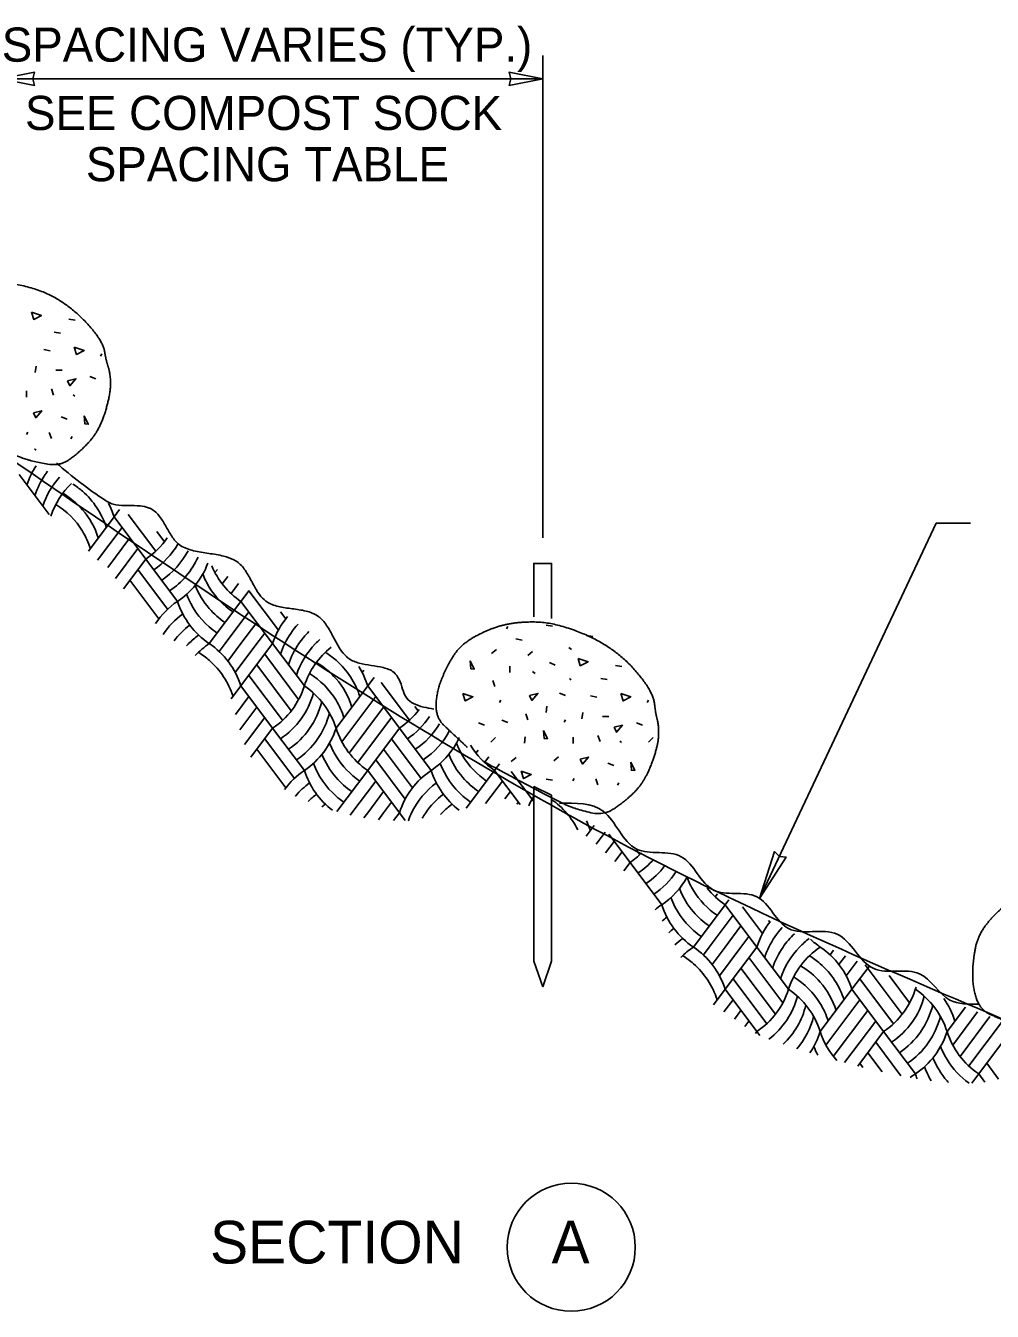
# Model space of a CAD drawing. Extents: x 99862 to 103680, y 99470 to 102076.
# Drawn here: x 101718 to 102171, y 100755 to 101357 of the extents above; entities that cross this region are included whole.
import ezdxf

# ---------------------------------------------------------------- set-up
doc = ezdxf.new("R2010")
doc.units = 0
for name, color, linetype in [('Level 1', 7, 'Continuous'), ('Level 15', 7, 'Continuous'), ('Level 2', 7, 'Continuous'), ('Level 20', 7, 'Continuous'), ('Level 5', 7, 'Continuous'), ('Level 8', 7, 'Continuous')]:
    doc.layers.add(name, color=color, linetype=linetype)

msp = doc.modelspace()

# ---------------------------------------------------------------- linework, layer by layer
at = {"layer": 'Level 1'}
for points in [[(101679, 101169.6), (101713.94, 101155.29), (101722.33, 101152.8), (101733.67, 101150.75), (101742.6, 101156.76), (101752.6, 101167.59), (101757.92, 101185.54), (101757.37, 101195.19), (101755.63, 101199.86), (101754.11, 101209.17), (101741.6, 101223.5), (101725.73, 101233.48), (101704.82, 101237.69), (101688.7, 101238.98), (101676.01, 101235.17), (101662.34, 101226.63), (101656.02, 101214.64), (101652.47, 101202.67), (101653.18, 101191.71), (101654.52, 101177.27), (101669.65, 101172.39)], [(101932.12, 101012.62), (101968.6, 100992.9), (101976.82, 100989.9), (101988.01, 100987.17), (101997.29, 100992.63), (102007.93, 101002.83), (102014.34, 101020.42), (102014.37, 101030.09), (102012.92, 101034.85), (102011.97, 101044.24), (102000.35, 101059.3), (101985.11, 101070.23), (101964.62, 101077.69), (101948.49, 101077.97), (101935.59, 101074.94), (101921.43, 101067.25), (101914.39, 101055.66), (101910.12, 101043.93), (101910.16, 101032.94), (101917.43, 101025.96), (101924.75, 101019.11)], [(102192.84, 100884.38), (102233.87, 100878.32), (102242.62, 100878.32), (102254.07, 100879.59), (102260.92, 100887.89), (102267.43, 100901.12), (102267.43, 100919.84), (102264.15, 100928.93), (102261.16, 100932.91), (102257.06, 100941.41), (102240.99, 100951.59), (102222.93, 100956.64), (102201.12, 100956.64), (102185.87, 100951.38), (102174.78, 100944.12), (102164.11, 100932.05), (102161.46, 100918.76), (102161.46, 100906.27), (102165.26, 100895.96), (102174.48, 100891.89), (102183.7, 100887.96)]]:
    msp.add_open_spline(points, degree=2, dxfattribs=at)
at = {"layer": 'Level 15'}
for p, q in [((101960.08, 101117.27), (101960.08, 101343.16)), ((101706.31, 101332.26), (101960.08, 101332.26)), ((102061.66, 100948.34), (102144.42, 101124.12)), ((102160.42, 101124.12), (102144.42, 101124.12))]:
    msp.add_line(p, q, dxfattribs=at)
for points in [[(101706.31, 101332.26), (101722.04, 101329.18), (101721.31, 101332.26), (101722.04, 101335.35)], [(101960.08, 101332.26), (101944.35, 101329.18), (101945.08, 101332.26), (101944.35, 101335.35)], [(102061.66, 100948.34), (102074.05, 100967.74), (102070.9, 100968.05), (102068.65, 100970.28)]]:
    msp.add_lwpolyline(points, close=True, dxfattribs=at)
at = {"layer": 'Level 2'}
for p, q in [((101738.12, 101219.69), (101741.07, 101219.16)), ((101731.23, 101213.61), (101734.19, 101213.07)), ((101726.42, 101205.43), (101729.37, 101204.9)), ((101753.59, 101203.47), (101752.97, 101202.37)), ((101722.76, 101197.65), (101722.39, 101194.67)), ((101731.97, 101195.74), (101734.97, 101195.74)), ((101747.97, 101192.83), (101750.76, 101191.71)), ((101718.32, 101186.14), (101718.32, 101183.14)), ((101730.94, 101184.13), (101729.93, 101186.96)), ((101740.15, 101184.23), (101740.93, 101183.6)), ((101734.55, 101173.97), (101737.34, 101172.85)), ((101718.85, 101166.71), (101718.23, 101165.61)), ((101729.93, 101163.73), (101728.92, 101166.55)), ((101739.68, 101164.67), (101739.06, 101163.58)), ((101721.98, 101158.89), (101722.76, 101158.26)), ((101943.77, 101075.78), (101943.15, 101074.69)), ((101961.68, 101076.37), (101964.63, 101075.83)), ((101947.51, 101069.88), (101950.46, 101069.35)), ((101980.52, 101071.54), (101983.48, 101071.01)), ((101936.14, 101063.01), (101938.42, 101064.96)), ((101953.03, 101062.1), (101955.3, 101064.05)), ((101972.38, 101065.93), (101973.63, 101064.99)), ((101963.19, 101058.79), (101965.97, 101057.67)), ((101944.63, 101057.2), (101944.63, 101054.2)), ((101955.34, 101054.67), (101956.59, 101053.73)), ((101994.14, 101057.44), (101997.1, 101056.91)), ((101937.69, 101047.68), (101936.68, 101050.5)), ((101972.69, 101051.38), (101973.47, 101050.76)), ((101987.26, 101051.36), (101990.21, 101050.82)), ((101940.42, 101041.22), (101939.79, 101040.12)), ((101968.01, 101044.45), (101970.8, 101043.34)), ((101982.45, 101043.18), (101985.4, 101042.65)), ((102009.62, 101041.22), (102009, 101040.12)), ((101953.11, 101031.98), (101952.1, 101034.8)), ((101961.97, 101038.4), (101961.68, 101035.41)), ((101978.79, 101035.4), (101978.42, 101032.42)), ((101988, 101033.49), (101991, 101033.49)), ((101930.02, 101030.57), (101932.81, 101029.46)), ((101940.92, 101031.82), (101943.74, 101030.81)), ((101970.82, 101031.98), (101970.19, 101030.89)), ((102004, 101030.57), (102006.78, 101029.46)), ((101935.71, 101021.61), (101937.91, 101023.65)), ((101951.87, 101024.07), (101951.58, 101021.08)), ((101974.34, 101023.89), (101974.34, 101020.89)), ((101986.96, 101021.88), (101985.96, 101024.7)), ((101996.18, 101021.97), (101996.96, 101021.35)), ((102009.69, 101021.61), (102011.88, 101023.65)), ((101945.34, 101012.47), (101947.62, 101014.42)), ((101965.24, 101012.77), (101967.52, 101014.72)), ((101990.58, 101011.72), (101993.37, 101010.6)), ((101961.68, 101004.26), (101964.63, 101003.72)), ((101974.88, 101004.46), (101974.25, 101003.36)), ((101985.96, 101001.48), (101984.95, 101004.3)), ((101955.9, 101000.8), (101955.9, 100918.89)), ((101964.25, 100996.64), (101955.9, 101000.8)), ((101995.71, 101002.42), (101995.08, 101001.33)), ((101964.25, 100918.89), (101964.25, 100996.64)), ((101955.9, 100918.89), (101960.08, 100907)), ((101960.08, 100907), (101964.25, 100918.89))]:
    msp.add_line(p, q, dxfattribs=at)
for points in [[(101720.57, 101223.02), (101721.67, 101219.58), (101725.26, 101221.46)], [(101740.62, 101206.6), (101741.72, 101203.16), (101745.31, 101205.03)], [(101737.49, 101190.79), (101738.59, 101188.45), (101741.4, 101191.73)], [(101721.53, 101175.85), (101722.63, 101173.5), (101725.44, 101176.78)], [(101745.31, 101174.37), (101747.19, 101170.46), (101745.62, 101170.62)], [(101926.11, 101059.67), (101927.99, 101055.76), (101926.42, 101055.92)], [(101976.6, 101060.77), (101977.69, 101057.33), (101981.29, 101059.2)], [(101922.67, 101044.35), (101923.77, 101040.9), (101927.36, 101042.78)], [(101953.93, 101043.46), (101955.03, 101041.12), (101957.84, 101044.4)], [(101996.65, 101044.35), (101997.74, 101040.9), (102001.34, 101042.78)], [(101993.52, 101028.54), (101994.61, 101026.2), (101997.43, 101029.48)], [(101960.37, 101027.06), (101962.24, 101023.15), (101960.68, 101023.3)], [(101977.56, 101013.59), (101978.65, 101011.25), (101981.47, 101014.53)], [(102001.34, 101012.12), (102003.21, 101008.21), (102001.65, 101008.37)], [(101950.03, 101007.9), (101951.12, 101004.46), (101954.72, 101006.33)]]:
    msp.add_lwpolyline(points, close=True, dxfattribs=at)
msp.add_lwpolyline([(101955.9, 101080.22), (101955.9, 101105.27), (101964.25, 101105.27), (101964.25, 101079.41)], dxfattribs=at)
at = {"layer": 'Level 20'}
msp.add_circle((101973.45, 100784.97), 30, dxfattribs=at)
at = {"layer": 'Level 5'}
for p, q in [((101714.79, 101146.88), (101728.85, 101128.13)), ((101759.34, 101127.08), (101761.89, 101130.48)), ((101747.28, 101111), (101759.34, 101127.08)), ((101759.34, 101127.08), (101774.19, 101107.29)), ((101765.97, 101128.14), (101778.84, 101110.98)), ((101751.55, 101106.8), (101763.05, 101122.13)), ((101779.3, 101120.27), (101782.92, 101115.44)), ((101756.39, 101103.35), (101766.76, 101117.18)), ((101759.96, 101098.22), (101770.48, 101112.23)), ((101763.79, 101093.42), (101774.19, 101107.29)), ((101774.19, 101107.29), (101789.04, 101087.49)), ((101770.48, 101102.34), (101784.38, 101083.79)), ((101806.56, 101100.95), (101807.67, 101102.42)), ((101766.76, 101097.39), (101780.31, 101079.33)), ((101810, 101095.64), (101812.64, 101099.16)), ((101814.08, 101091.18), (101817.6, 101095.87)), ((101818.74, 101087.49), (101822.55, 101092.57)), ((101822.45, 101092.44), (101836.26, 101074.02)), ((101803.89, 101067.69), (101818.74, 101087.49)), ((101811.31, 101067.69), (101822.45, 101082.54)), ((101818.74, 101087.49), (101833.58, 101067.69)), ((101837.31, 101082.52), (101839.7, 101079.33)), ((101818.74, 101067.69), (101826.16, 101077.59)), ((101826.16, 101067.69), (101829.87, 101072.64)), ((101808.54, 101063.99), (101811.31, 101067.69)), ((101812.62, 101059.53), (101818.74, 101067.69)), ((101816.06, 101054.22), (101826.16, 101067.69)), ((101818.74, 101047.89), (101833.58, 101067.69)), ((101833.58, 101067.69), (101848.43, 101047.89)), ((101826.16, 101057.79), (101842.32, 101036.25)), ((101829.87, 101062.74), (101845.76, 101041.55)), ((101822.45, 101052.84), (101838.24, 101031.78)), ((101875.46, 101054.22), (101876.23, 101055.25)), ((101878.13, 101047.89), (101881.07, 101051.81)), ((101814.18, 101041.81), (101818.74, 101047.89)), ((101818.74, 101047.89), (101833.58, 101028.09)), ((101863.28, 101028.09), (101878.13, 101047.89)), ((101878.13, 101047.89), (101892.98, 101028.09)), ((101884.36, 101049.49), (101897.64, 101031.78)), ((101816.11, 101034.49), (101822.45, 101042.94)), ((101865.96, 101021.76), (101881.84, 101042.94)), ((101818.16, 101027.32), (101826.16, 101037.99)), ((101869.4, 101016.45), (101885.56, 101037.99)), ((101900.16, 101038.32), (101901.71, 101036.25)), ((101820.38, 101020.39), (101829.87, 101033.04)), ((101823.42, 101014.53), (101833.58, 101028.09)), ((101833.58, 101028.09), (101848.43, 101008.29)), ((101873.48, 101011.98), (101889.27, 101033.04)), ((101878.13, 101008.29), (101892.98, 101028.09)), ((101892.98, 101028.09), (101907.83, 101008.29)), ((101829.87, 101023.14), (101843.78, 101004.6)), ((101889.27, 101023.14), (101903.18, 101004.6)), ((101826.16, 101018.19), (101839.7, 101000.13)), ((101885.56, 101018.19), (101899.1, 101000.13)), ((101928.8, 101016.45), (101929.76, 101017.73)), ((101881.84, 101013.24), (101895.66, 100994.82)), ((101932.87, 101011.98), (101934.88, 101014.66)), ((101937.53, 101008.29), (101939.85, 101011.38)), ((101863.7, 100989.04), (101878.13, 101008.29)), ((101870.71, 100988.49), (101881.84, 101003.34)), ((101878.13, 101008.29), (101892.98, 100988.49)), ((101924.24, 100990.57), (101937.53, 101008.29)), ((101933.3, 100992.76), (101941.24, 101003.34)), ((101937.53, 101008.29), (101949.44, 100992.4)), ((101945.36, 101007.75), (101955.9, 100993.69)), ((101878.13, 100988.49), (101885.56, 100998.39)), ((101942.37, 100994.95), (101944.95, 100998.39)), ((101885.56, 100988.49), (101889.27, 100993.44)), ((101947.95, 100992.49), (101948.66, 100993.44)), ((101869.89, 100987.4), (101870.71, 100988.49)), ((101876.34, 100986.1), (101878.13, 100988.49)), ((101883.1, 100985.22), (101885.56, 100988.49)), ((101890.22, 100984.81), (101892.98, 100988.49)), ((101892.98, 100988.49), (101895.7, 100984.86)), ((101980.5, 100977.5), (101984.24, 100982.49)), ((101985.09, 100973.73), (101989.37, 100979.43)), ((101989.54, 100969.75), (101993.54, 100975.09)), ((101991.01, 100978.46), (102000.96, 100965.19)), ((101993.85, 100965.61), (101997.25, 100970.14)), ((102004.07, 100970.95), (102005.62, 100968.88)), ((101998.05, 100961.3), (102000.96, 100965.19)), ((102000.96, 100965.19), (102015.81, 100945.39)), ((102040.85, 100949.08), (102041.97, 100950.57)), ((102030.66, 100925.59), (102045.51, 100945.39)), ((102045.51, 100945.39), (102047.29, 100947.76)), ((102045.51, 100945.39), (102060.36, 100925.59)), ((102053.69, 100944.38), (102063.03, 100931.92)), ((102038.08, 100925.59), (102049.22, 100940.44)), ((102065.87, 100938.04), (102066.48, 100937.23)), ((102045.51, 100925.59), (102052.93, 100935.49)), ((102035.31, 100921.9), (102038.08, 100925.59)), ((102039.39, 100917.43), (102045.51, 100925.59)), ((102042.83, 100912.12), (102052.93, 100925.59)), ((102045.51, 100905.79), (102060.36, 100925.59)), ((102052.93, 100925.59), (102056.65, 100930.54)), ((102060.36, 100925.59), (102075.21, 100905.79)), ((102056.65, 100920.64), (102072.53, 100899.46)), ((102094.71, 100921.9), (102096.34, 100924.07)), ((102098.79, 100917.43), (102101.84, 100921.51)), ((102102.23, 100912.12), (102107.36, 100918.97)), ((102052.93, 100915.69), (102069.09, 100894.15)), ((102104.9, 100905.79), (102112.91, 100916.46)), ((102111.16, 100917.24), (102128.49, 100894.15)), ((102049.22, 100910.74), (102065.01, 100889.68)), ((102108.62, 100910.74), (102124.41, 100889.68)), ((102122.32, 100912.27), (102131.93, 100899.46)), ((102040.08, 100898.56), (102045.51, 100905.79)), ((102045.51, 100905.79), (102060.36, 100885.99)), ((102090.06, 100885.99), (102104.9, 100905.79)), ((102104.9, 100905.79), (102119.75, 100885.99)), ((102044.96, 100895.16), (102049.22, 100900.84)), ((102049.84, 100891.77), (102052.93, 100895.89)), ((102092.73, 100879.66), (102108.62, 100900.84)), ((102096.17, 100874.35), (102112.33, 100895.89)), ((102149.45, 100885.99), (102158.03, 100897.42)), ((102152.13, 100879.66), (102163.78, 100895.19)), ((102054.73, 100888.38), (102056.65, 100890.94)), ((102101.42, 100871.44), (102116.04, 100890.94)), ((102155.57, 100874.35), (102169.56, 100893)), ((102159.65, 100869.89), (102175.37, 100890.85)), ((102059.67, 100885.07), (102060.36, 100885.99)), ((102060.36, 100885.99), (102061.69, 100884.21)), ((102107.63, 100869.83), (102119.75, 100885.99)), ((102119.75, 100885.99), (102134.6, 100866.19)), ((102164.3, 100866.19), (102179.15, 100885.99)), ((102116.04, 100881.04), (102127.88, 100865.25)), ((102108.62, 100871.14), (102110.06, 100869.22)), ((102112.33, 100876.09), (102119.08, 100867.1)), ((102168.01, 100871.14), (102173.57, 100863.73)), ((102161.01, 100861.81), (102164.3, 100866.19)), ((102164.3, 100866.19), (102167.18, 100862.35))]:
    msp.add_line(p, q, dxfattribs=at)
for centre, start, end in [((101754.31, 101130.54), 147.04348, 154.2266), ((101758.03, 101125.59), 142.63383, 145.49109), ((101754.31, 101130.54), 154.22654, 162.3566), ((101758.03, 101125.59), 145.49102, 162.3566), ((101761.74, 101120.64), 138.2671, 162.3566), ((101765.45, 101115.69), 133.92125, 161.82674), ((101719.82, 101110.74), 48.95968, 57.50791), ((101716.11, 101105.8), 40.94134, 59.30215), ((101719.82, 101110.74), 17.6434, 48.95975), ((101712.39, 101100.85), 31.33163, 58.48737), ((101716.11, 101105.8), 17.6434, 40.94141), ((101723.53, 101115.69), 17.6434, 28.13836), ((101712.39, 101100.85), 17.6434, 31.33172), ((101753.23, 101138.47), 303.90361, 325.62844), ((101756.94, 101133.52), 303.90361, 329.07617), ((101760.65, 101128.57), 303.90361, 332.4727), ((101764.37, 101123.62), 303.90361, 335.83607), ((101768.08, 101118.67), 303.90361, 339.18329), ((101835.98, 101113.72), 200.87781, 211.33197), ((101839.7, 101118.67), 202.77975, 236.09639), ((101832.27, 101108.77), 201.43438, 220.94161), ((101835.98, 101113.72), 211.33188, 236.09639), ((101828.56, 101103.83), 200.24322, 228.95992), ((101810, 101056.3), 123.90361, 146.44771), ((101813.71, 101051.35), 126.30625, 146.65479), ((101824.85, 101098.88), 197.6434, 236.09639), ((101832.27, 101108.77), 220.94154, 236.09639), ((101817.42, 101046.4), 127.1006, 142.90441), ((101869.39, 101056.3), 140.26238, 162.3566), ((101873.11, 101051.35), 137.26305, 154.2266), ((101821.14, 101041.45), 126.331, 135.71278), ((101828.56, 101103.83), 228.95986, 236.09639), ((101876.82, 101046.4), 134.26616, 145.49109), ((101880.53, 101041.45), 131.26099, 135.71278), ((101821.14, 101041.45), 135.71269, 137.83054), ((101824.85, 101036.5), 123.90361, 137.10297), ((101779.21, 101031.55), 48.95968, 58.54646), ((101782.93, 101036.5), 17.6434, 56.09634), ((101873.11, 101051.35), 154.22654, 162.3566), ((101876.82, 101046.4), 145.49102, 162.3566), ((101880.53, 101041.45), 135.71269, 162.3566), ((101884.24, 101036.5), 128.23593, 162.3566), ((101838.61, 101031.55), 48.95968, 58.54646), ((101779.21, 101031.55), 17.6434, 48.95975), ((101834.9, 101026.6), 40.94134, 59.30215), ((101838.61, 101031.55), 17.6434, 48.95975), ((101831.19, 101021.65), 31.33163, 58.48737), ((101842.32, 101036.5), 17.6434, 32.91319), ((101812.62, 101059.28), 303.90361, 342.3566), ((101827.47, 101016.7), 17.6434, 56.09639), ((101834.9, 101026.6), 17.6434, 40.94141), ((101816.34, 101054.33), 303.90361, 345.01126), ((101820.05, 101049.38), 303.90361, 346.31988), ((101831.18, 101021.65), 17.6434, 31.33172), ((101823.76, 101044.43), 303.90361, 345.77133), ((101872.02, 101059.28), 303.90361, 323.41919), ((101875.73, 101054.33), 303.90361, 326.34128), ((101827.47, 101039.48), 303.90361, 342.3566), ((101899.09, 101039.48), 197.64354, 236.09639), ((101879.44, 101049.38), 303.90361, 329.28276), ((101883.16, 101044.43), 303.90361, 332.25355), ((101886.87, 101039.48), 303.90361, 335.26386), ((101891.67, 101029.58), 201.43438, 220.94161), ((101895.38, 101034.53), 200.87781, 211.33197), ((101951.06, 101029.58), 201.43438, 220.94161), ((101954.78, 101034.53), 200.87781, 211.33197), ((101958.49, 101039.48), 211.02528, 236.09639), ((101887.96, 101024.63), 200.24322, 228.95992), ((101895.38, 101034.53), 211.33188, 236.09639), ((101947.35, 101024.63), 200.24322, 228.95992), ((101954.78, 101034.53), 211.33188, 236.09639), ((101869.39, 100977.1), 123.90361, 143.56361), ((101884.24, 101019.68), 197.6434, 233.07643), ((101891.67, 101029.58), 220.94154, 236.09639), ((101928.79, 100977.1), 123.90361, 162.3566), ((101943.64, 101019.68), 197.6434, 232.7619), ((101951.06, 101029.58), 220.94154, 236.09639), ((101873.11, 100972.15), 126.30625, 139.79277), ((101932.5, 100972.15), 126.30625, 154.2266), ((101873.11, 100972.15), 139.79277, 140.06458), ((101876.82, 100967.2), 127.1006, 135.1103), ((101880.53, 100962.25), 126.331, 129.4638), ((101887.96, 101024.63), 228.95986, 236.09639), ((101936.22, 100967.2), 127.1006, 145.49109), ((101939.93, 100962.25), 126.331, 135.71278), ((101947.35, 101024.63), 228.95986, 236.09639), ((101988.19, 100977.1), 149.2231, 157.0397), ((101942.88, 100963.7), 40.94134, 55.33077), ((101932.5, 100972.15), 154.22654, 160.12324), ((101936.22, 100967.2), 145.49102, 150.01098), ((101939.93, 100962.25), 135.71269, 137.42536), ((101942.88, 100963.7), 26.56911, 40.94141), ((101932.5, 100972.15), 160.12324, 160.38113), ((101946.59, 100968.65), 17.6434, 25.3276), ((101980, 100996.38), 303.90361, 314.64231), ((101983.71, 100991.43), 303.90361, 318.65298), ((101987.43, 100986.48), 303.90361, 322.74442), ((101991.14, 100981.53), 303.90361, 326.74538), ((101994.85, 100976.58), 303.90361, 330.74166), ((102062.76, 100971.63), 200.94295, 211.33197), ((102059.05, 100966.68), 201.43438, 220.94161), ((102062.76, 100971.63), 211.33188, 236.09639), ((102066.47, 100976.58), 218.507, 236.09639), ((102036.77, 100914.2), 123.90361, 129.89547), ((102051.62, 100956.78), 197.6434, 236.09639), ((102055.33, 100961.73), 200.24322, 228.95992), ((102040.48, 100909.25), 126.30625, 130.65127), ((102059.04, 100966.68), 220.94154, 236.09639), ((102096.17, 100914.2), 141.51803, 162.3566), ((102044.2, 100904.3), 127.1006, 131.85725), ((102055.33, 100961.73), 228.95986, 236.09639), ((102099.88, 100909.25), 137.27207, 154.2266), ((102103.59, 100904.3), 132.8919, 145.49109), ((102047.91, 100899.35), 126.331, 133.52839), ((102051.62, 100894.4), 123.90361, 135.4672), ((102009.7, 100894.4), 17.6434, 56.09634), ((102099.88, 100909.25), 154.22654, 162.3566), ((102103.59, 100904.3), 145.49102, 162.3566), ((102107.3, 100899.35), 135.71269, 162.3566), ((102111.02, 100894.4), 123.90361, 162.3566), ((102107.3, 100899.35), 126.63093, 135.71278), ((102111.02, 100956.78), 227.14546, 236.09639), ((102069.09, 100894.4), 17.6434, 56.09634), ((102005.99, 100889.45), 48.95968, 58.54646), ((102065.38, 100889.45), 48.95968, 58.54646), ((102005.99, 100889.45), 17.6434, 48.95975), ((102061.67, 100884.5), 40.94134, 59.30215), ((102065.38, 100889.45), 17.6434, 48.95975), ((102057.96, 100879.55), 31.33163, 58.48737), ((102061.67, 100884.5), 17.6434, 40.94141), ((102039.4, 100917.18), 303.90361, 342.3566), ((102043.11, 100912.23), 307.63483, 345.01126), ((102054.25, 100874.6), 17.6434, 56.09639), ((102098.79, 100917.18), 303.90361, 344.02533), ((102102.51, 100912.23), 303.90361, 345.01126), ((102113.64, 100874.6), 17.6434, 56.09639), ((102117.35, 100879.55), 17.6434, 35.67571), ((102046.82, 100907.28), 313.55521, 346.31988), ((102057.96, 100879.55), 17.6434, 31.33172), ((102106.22, 100907.28), 303.90361, 346.31988), ((102117.35, 100879.55), 31.33163, 32.29042), ((102050.53, 100902.33), 319.48388, 345.77133), ((102109.93, 100902.33), 303.90361, 345.77133), ((102054.25, 100897.38), 325.37573, 342.3566), ((102125.87, 100897.38), 197.64354, 221.62197), ((102113.64, 100897.38), 303.90361, 342.3566), ((102185.26, 100897.38), 197.64354, 236.09639), ((102122.15, 100892.43), 200.87781, 207.77475), ((102181.55, 100892.43), 200.87781, 211.33197), ((102177.84, 100887.48), 201.43438, 220.94161), ((102181.55, 100892.43), 211.33188, 234.67041), ((102155.56, 100835), 123.90361, 128.41445), ((102170.41, 100877.58), 197.6434, 201.34998), ((102174.13, 100882.53), 200.24322, 211.45927), ((102177.84, 100887.48), 220.94154, 222.5353)]:
    msp.add_arc(centre, 37.58, start, end, dxfattribs=at)
msp.add_spline([(101701.91, 101160.36), (102021.08, 100961.71), (102190.93, 100885.35)], degree=3, dxfattribs=at)
at = {"layer": 'Level 8'}
for points in [[(101732.28, 101152.23), (101755.24, 101134.78), (101757.57, 101133.48), (101760.15, 101132.77), (101765.79, 101132.38), (101771.5, 101132.19), (101775.45, 101131.33), (101776.06, 101131.08), (101776.65, 101130.79), (101778.8, 101129.25), (101780.63, 101127.23), (101783.7, 101122.38), (101786.69, 101117.45), (101788.41, 101115.34), (101790.41, 101113.67), (101793.33, 101112.19), (101796.58, 101111.19), (101803.63, 101109.95), (101810.68, 101108.68), (101815.42, 101106.94), (101816.13, 101106.54), (101816.82, 101106.1), (101818.92, 101104.29), (101820.71, 101102.03), (101823.77, 101096.8), (101826.82, 101091.55), (101829.58, 101088.31), (101830.66, 101087.45), (101836.26, 101085.11), (101842.73, 101084.03), (101849.2, 101082.94), (101854.8, 101080.58), (101855.94, 101079.67), (101856.98, 101078.63), (101858.85, 101076.23), (101862.06, 101070.67), (101865.24, 101065.1), (101868.11, 101061.63), (101869.23, 101060.71), (101874.08, 101058.57), (101879.74, 101057.51), (101885.4, 101056.45), (101890.26, 101054.32), (101892.79, 101050.9), (101894.47, 101046.37), (101896.37, 101042.16), (101899.56, 101039.68), (101909.1, 101037.07)], [(101967.97, 100992.95), (101988.41, 100989.19), (102004.07, 100971.46), (102024.97, 100967.9), (102040, 100952.29), (102060.36, 100949.11), (102075.24, 100934.22), (102097.96, 100931.6), (102115.1, 100915.46), (102136.57, 100913.05), (102150.8, 100900.77), (102164.25, 100898.85)]]:
    msp.add_spline(points, degree=3, dxfattribs=at)

# ---------------------------------------------------------------- texts
at = {"layer": 'Level 20'}
for s, height, p in [('SPACING VARIES (TYP.)', 16, (101706.71, 101340.26)), ('SEE COMPOST SOCK ', 16, (101717.58, 101308.26)), ('SPACING TABLE', 16, (101746.1, 101284.26)), ('SECTION', 20, (101804.26, 100777.36)), ('A', 20, (101964.21, 100777.36))]:
    msp.add_text(s, height=height, dxfattribs=at).set_placement(p)

doc.saveas('drawing.dxf')
